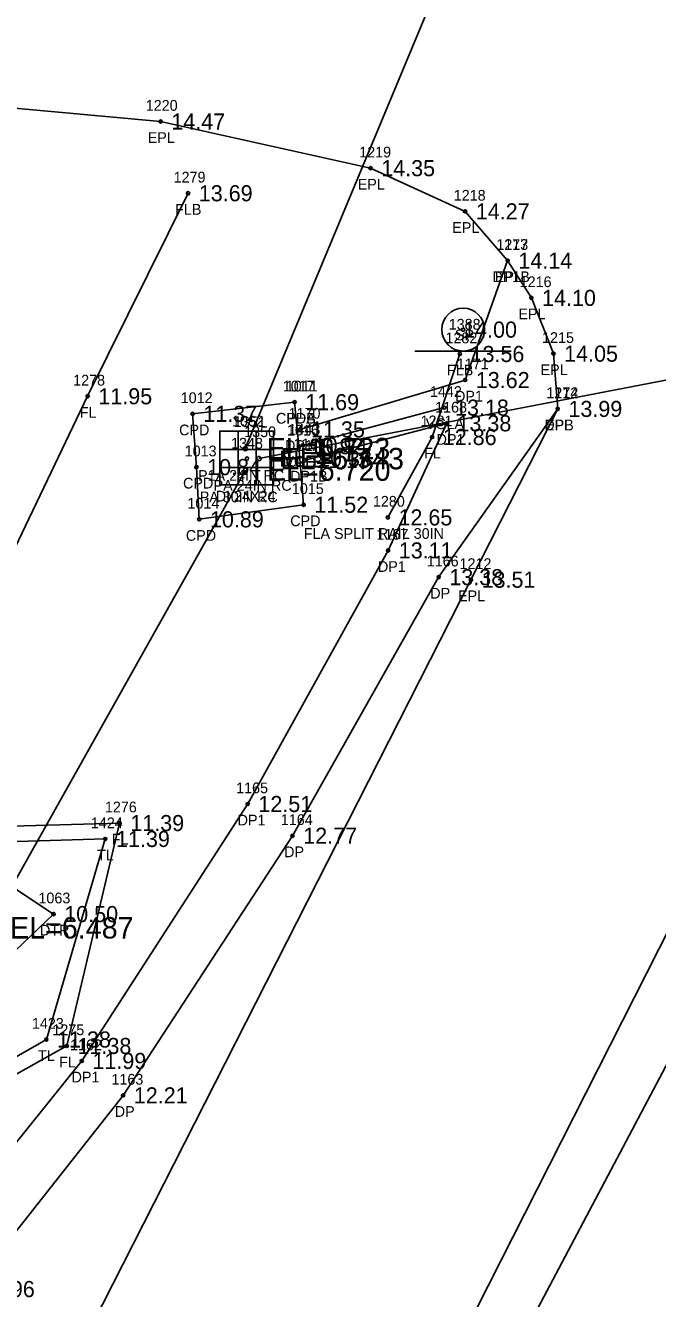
# Model space of a CAD drawing. Extents: x 2072307 to 2072993, y 127574 to 129736.
# Drawn here: x 2072771.4 to 2072830.3, y 128472.9 to 128591.5 of the extents above; entities that cross this region are included whole.
import ezdxf

# ---------------------------------------------------------------- set-up
doc = ezdxf.new("R2010")
doc.units = 0
for name, color, linetype in [('RD_EX_BldgApp', 7, 'Continuous'), ('RD_EX_BldgApp_txCode', 7, 'Continuous'), ('RD_EX_Conc', 7, 'Continuous'), ('RD_EX_Conc_txCode', 7, 'Continuous'), ('RD_EX_DR_Inlet', 7, 'Continuous'), ('RD_EX_DR_Inlet_txCode', 7, 'Continuous'), ('RD_EX_DR_Pipe', 7, 'Continuous'), ('RD_EX_DR_Pipe_txCode', 7, 'Continuous'), ('RD_EX_Driveway', 7, 'Continuous'), ('RD_EX_Driveway_txCode', 7, 'Continuous'), ('RD_EX_Fence_Other', 7, 'Continuous'), ('RD_EX_Fence_Other_txCode', 7, 'Continuous'), ('RD_EX_H2O', 7, 'Continuous'), ('RD_EX_H2O_txCode', 7, 'Continuous'), ('RD_EX_Road', 7, 'Continuous'), ('RD_EX_Road_txCode', 7, 'Continuous'), ('RD_EX_TX_BldgApp_ELEV', 7, 'Continuous'), ('RD_EX_TX_Conc_ELEV', 7, 'Continuous'), ('RD_EX_TX_DR_Inlet_ELEV', 7, 'Continuous'), ('RD_EX_TX_Driveway_ELEV', 7, 'Continuous'), ('RD_EX_TX_Fence_Other_ELEV', 7, 'Continuous'), ('RD_EX_TX_H2O_ELEV', 7, 'Continuous'), ('RD_EX_TX_Road_ELEV', 7, 'Continuous'), ('RD_EX_TX_VEG_ELEV', 7, 'Continuous'), ('RD_EX_VEG', 7, 'Continuous'), ('RD_EX_VEG_txCode', 7, 'Continuous'), ('RD_SMD_Locator', 7, 'Continuous'), ('RD_TX_Pipe_ElevEX', 7, 'Continuous')]:
    doc.layers.add(name, color=color, linetype=linetype)

msp = doc.modelspace()

# ---------------------------------------------------------------- linework, layer by layer
at = {"layer": 'RD_EX_BldgApp'}
msp.add_line((2072807.67, 128561.15), (2072816.67, 128561.15), dxfattribs=at)
msp.add_circle((2072812.19, 128563.17), 2, dxfattribs=at)
at = {"layer": 'RD_EX_Conc'}
msp.add_lwpolyline([(2072796.46, 128556.41), (2072786.95, 128555.32), (2072787.31, 128550.36), (2072787.57, 128545.49), (2072797.31, 128546.85), (2072796.87, 128552.3), (2072796.46, 128556.41)], dxfattribs=at)
at = {"layer": 'RD_EX_DR_Inlet'}
for p, q in [((2072791.19, 128553.71), (2072791.19, 128548.71)), ((2072792.89, 128553.71), (2072792.89, 128548.71)), ((2072789.49, 128552.01), (2072794.49, 128552.01)), ((2072789.49, 128550.31), (2072794.49, 128550.31))]:
    msp.add_line(p, q, dxfattribs=at)
msp.add_lwpolyline([(2072789.49, 128548.71), (2072789.49, 128553.71), (2072794.49, 128553.71), (2072794.49, 128548.71)], close=True, dxfattribs=at)
at = {"layer": 'RD_EX_DR_Pipe'}
for p, q in [((2072791.86, 128552.08), (2072822.76, 128626.35)), ((2072793.14, 128551.15), (2072922.75, 128576.12)), ((2072791.89, 128550.08), (2072767.92, 128507.42))]:
    msp.add_line(p, q, dxfattribs=at)
at = {"layer": 'RD_EX_Driveway'}
for points in [[(2072797, 128553.87), (2072812.37, 128558.47), (2072816.34, 128569.6)], [(2072694.21, 128239.74), (2072695.7, 128289.15), (2072695.56, 128330.43), (2072696.37, 128337.85), (2072700.81, 128345.17), (2072711.22, 128347.96), (2072719.56, 128349.59), (2072725.15, 128351.26), (2072733.07, 128358.33), (2072734.19, 128365.42), (2072741.79, 128414.16), (2072748.82, 128445.27), (2072754.15, 128456.57), (2072759.92, 128465.41), (2072766.21, 128473.75), (2072780.47, 128491.8), (2072796.27, 128516), (2072809.9, 128540.1), (2072821.01, 128555.78)], [(2072689.37, 128239.9), (2072690.93, 128289.43), (2072690.32, 128330.24), (2072690.73, 128338.81), (2072697.63, 128350.77), (2072709.38, 128353.48), (2072719, 128355.15), (2072723.52, 128356.83), (2072727.18, 128360.82), (2072729.07, 128366.04), (2072736.87, 128415.65), (2072743.44, 128446.63), (2072749.73, 128459.37), (2072755.76, 128468.63), (2072761.76, 128476.56), (2072776.61, 128495.01), (2072792.09, 128518.96), (2072805.19, 128542.59), (2072810.66, 128554.44), (2072797.46, 128551.01)]]:
    msp.add_lwpolyline(points, dxfattribs=at)
at = {"layer": 'RD_EX_Fence_Other'}
for points in [[(2072717.23, 128356.49), (2072726.05, 128417.31), (2072734.38, 128449.46), (2072744.93, 128479.47), (2072775.22, 128496.41), (2072780.14, 128517.18), (2072757.78, 128516.55), (2072777.16, 128556.96), (2072786.53, 128575.88)], [(2072805.16, 128545.67), (2072809.29, 128553.16), (2072811.88, 128560.9)]]:
    msp.add_lwpolyline(points, dxfattribs=at)
at = {"layer": 'RD_EX_H2O'}
msp.add_lwpolyline([(2072699.9, 128366.65), (2072717.3, 128368.56), (2072719.94, 128447.6), (2072741.08, 128477.29), (2072773.98, 128508.7), (2072764.73, 128514.82)], dxfattribs=at)
at = {"layer": 'RD_EX_Road'}
msp.add_line((2072810.43, 128555.9), (2072797.24, 128552.38), dxfattribs=at)
for points in [[(2072789.45, 128345.69), (2072789.46, 128382.93), (2072788.01, 128408.09), (2072794.06, 128431.26), (2072804.3, 128453.88), (2072840.7, 128525.64), (2072876.68, 128596.08), (2072888.72, 128617.36), (2072893.24, 128622.62), (2072899.84, 128627.36), (2072910.72, 128631.76), (2072918.79, 128632.23), (2072935.82, 128627.02), (2072957.37, 128619.98)], [(2072775.68, 128466.69), (2072812.91, 128539.86), (2072821.01, 128555.78), (2072820.61, 128560.93), (2072818.55, 128566.13), (2072816.34, 128569.6), (2072812.37, 128574.19), (2072803.55, 128578.22), (2072783.97, 128582.57), (2072748.23, 128585.83), (2072732.11, 128585.24), (2072729.74, 128580.26), (2072735.29, 128576), (2072744.65, 128575.04), (2072744.47, 128530.69), (2072748.67, 128517.7), (2072747.55, 128516.74), (2072744.67, 128526.22), (2072742.83, 128527.54), (2072739.81, 128528.33), (2072729.54, 128527.67)]]:
    msp.add_lwpolyline(points, dxfattribs=at)
at = {"layer": 'RD_EX_VEG'}
for points in [[(2072791.29, 128345.62), (2072800.72, 128429.53), (2072808.9, 128452.58), (2072870.32, 128568.64), (2072876.57, 128573.6), (2072916.77, 128564.68), (2072920.97, 128548.67)], [(2072681.97, 128364.24), (2072716.35, 128365.68), (2072731.52, 128450.35), (2072742.94, 128479.7), (2072773.31, 128497.01), (2072778.81, 128515.7), (2072758.24, 128515.09)]]:
    msp.add_lwpolyline(points, dxfattribs=at)
at = {"layer": 'RD_SMD_Locator'}
for centre, radius in [((2072783.97, 128582.57), 0.15), ((2072803.55, 128578.22), 0.15), ((2072786.53, 128575.88), 0.15), ((2072812.37, 128574.19), 0.15), ((2072816.34, 128569.6), 0.15), ((2072816.34, 128569.6), 0.15), ((2072818.55, 128566.13), 0.15), ((2072812.19, 128563.17), 0.15), ((2072811.88, 128560.9), 0.15), ((2072820.61, 128560.93), 0.15), ((2072812.37, 128558.47), 0.15), ((2072777.16, 128556.96), 0.15), ((2072796.46, 128556.41), 0.15), ((2072796.46, 128556.41), 0.15), ((2072786.95, 128555.32), 0.15), ((2072810.43, 128555.9), 0.15), ((2072821.01, 128555.78), 0.15), ((2072821.01, 128555.78), 0.15), ((2072810.66, 128554.44), 0.15), ((2072797, 128553.87), 0.15), ((2072809.29, 128553.16), 0.15), ((2072791.86, 128552.08), 0.2), ((2072796.87, 128552.3), 0.15), ((2072797.24, 128552.38), 0.15), ((2072792.03, 128551.15), 0.15), ((2072793.14, 128551.15), 0.2), ((2072797.46, 128551.01), 0.15), ((2072787.31, 128550.36), 0.15), ((2072791.89, 128550.08), 0.2), ((2072797.31, 128546.85), 0.15), ((2072805.16, 128545.67), 0.15), ((2072787.57, 128545.49), 0.15), ((2072805.19, 128542.59), 0.15), ((2072809.9, 128540.1), 0.15), ((2072812.91, 128539.86), 0.15), ((2072792.09, 128518.96), 0.15), ((2072780.14, 128517.18), 0.15), ((2072796.27, 128516), 0.15), ((2072778.81, 128515.7), 0.15), ((2072773.98, 128508.7), 0.15), ((2072773.31, 128497.01), 0.15), ((2072775.22, 128496.41), 0.15), ((2072776.61, 128495.01), 0.15), ((2072780.47, 128491.8), 0.15)]:
    msp.add_circle(centre, radius, dxfattribs=at)

# ---------------------------------------------------------------- texts
at = {"layer": 'RD_EX_BldgApp_txCode'}
for s, p in [('1388', (2072810.84, 128563.17)), ('SP', (2072811.41, 128562.17))]:
    msp.add_text(s, height=1, dxfattribs=at).set_placement(p)
at = {"layer": 'RD_EX_Conc_txCode'}
for s, p in [('1017', (2072795.36, 128557.41)), ('1011', (2072795.64, 128557.41)), ('1012', (2072785.84, 128556.32)), ('CPDA', (2072794.72, 128554.41)), ('CPDB', (2072794.73, 128554.41)), ('CPD', (2072785.69, 128553.32)), ('1016', (2072795.75, 128553.3)), ('1013', (2072786.21, 128551.36)), ('CPD', (2072795.62, 128550.3)), ('CPD', (2072786.06, 128548.36)), ('1015', (2072796.21, 128547.85)), ('1014', (2072786.47, 128546.49)), ('CPD', (2072796.06, 128544.85)), ('CPD', (2072786.32, 128543.49))]:
    msp.add_text(s, height=1, dxfattribs=at).set_placement(p)
at = {"layer": 'RD_EX_DR_Inlet_txCode'}
for s, p in [('1062', (2072790.62, 128554.15)), ('DI 24X24', (2072789.11, 128547.15))]:
    msp.add_text(s, height=1, dxfattribs=at).set_placement(p)
at = {"layer": 'RD_EX_DR_Pipe_txCode'}
for s, p in [('1351', (2072790.8, 128554.08)), ('1350', (2072791.76, 128553.15)), ('1348', (2072790.54, 128552.08)), ('P1A 24IN RC', (2072787.46, 128549.08)), ('PA 24IN RC', (2072788.91, 128548.15)), ('PA 30IN RC', (2072787.61, 128547.08))]:
    msp.add_text(s, height=1, dxfattribs=at).set_placement(p)
at = {"layer": 'RD_EX_Driveway_txCode'}
for s, p in [('1173', (2072815.28, 128570.6)), ('DP1B', (2072814.92, 128567.6)), ('1171', (2072811.59, 128559.47)), ('1172', (2072819.95, 128556.78)), ('1168', (2072809.57, 128555.44)), ('DP1', (2072811.43, 128556.47)), ('1170', (2072795.9, 128554.87)), ('DPB', (2072819.76, 128553.78)), ('1169', (2072796.38, 128552.01)), ('DP1', (2072809.71, 128552.44)), ('DP1A', (2072795.57, 128551.87)), ('DP1B', (2072796.05, 128549.01)), ('1167', (2072804.1, 128543.59)), ('DP1', (2072804.24, 128540.59)), ('1166', (2072808.79, 128541.1)), ('DP', (2072809.12, 128538.1)), ('1165', (2072791.01, 128519.96)), ('DP1', (2072791.15, 128516.96)), ('1164', (2072795.18, 128517)), ('DP', (2072795.49, 128514)), ('1162', (2072775.52, 128496.01)), ('DP1', (2072775.66, 128493.01)), ('1163', (2072779.38, 128492.8)), ('DP', (2072779.69, 128489.8))]:
    msp.add_text(s, height=1, dxfattribs=at).set_placement(p)
at = {"layer": 'RD_EX_Fence_Other_txCode'}
for s, p in [('1279', (2072785.18, 128576.88)), ('FLB', (2072785.32, 128573.88)), ('1282', (2072810.54, 128561.9)), ('1278', (2072775.81, 128557.96)), ('FLB', (2072810.68, 128558.9)), ('FL', (2072776.43, 128554.96)), ('1281', (2072808.22, 128554.16)), ('FL', (2072808.55, 128551.16)), ('1280', (2072803.77, 128546.67)), ('FLA SPLIT RAIL 30IN', (2072797.32, 128543.67)), ('1276', (2072778.77, 128518.18)), ('FL', (2072779.41, 128515.18)), ('1275', (2072773.87, 128497.41)), ('FL', (2072774.49, 128494.41))]:
    msp.add_text(s, height=1, dxfattribs=at).set_placement(p)
at = {"layer": 'RD_EX_H2O_txCode'}
for s, p in [('1063', (2072772.57, 128509.7)), ('DTR', (2072772.71, 128506.7))]:
    msp.add_text(s, height=1, dxfattribs=at).set_placement(p)
at = {"layer": 'RD_EX_Road_txCode'}
for s, p in [('1220', (2072782.58, 128583.57)), ('EPL', (2072782.76, 128580.57)), ('1219', (2072802.49, 128579.22)), ('EPL', (2072802.35, 128576.22)), ('1218', (2072811.31, 128575.19)), ('EPL', (2072811.17, 128572.19)), ('1217', (2072815.28, 128570.6)), ('EPL', (2072815.14, 128567.6)), ('1216', (2072817.46, 128567.13)), ('EPL', (2072817.34, 128564.13)), ('1215', (2072819.55, 128561.93)), ('EPL', (2072819.41, 128558.93)), ('1442', (2072809.09, 128556.9)), ('1214', (2072819.95, 128556.78)), ('1443', (2072795.89, 128553.38)), ('VGLA', (2072808.7, 128553.9)), ('EPL', (2072819.81, 128553.78)), ('VGLB', (2072795.52, 128550.38)), ('1212', (2072811.85, 128540.86)), ('EPL', (2072811.71, 128537.86))]:
    msp.add_text(s, height=1, dxfattribs=at).set_placement(p)
at = {"layer": 'RD_EX_TX_BldgApp_ELEV'}
msp.add_text('14.00', height=1.5, dxfattribs=at).set_placement((2072812.19, 128562.42))
at = {"layer": 'RD_EX_TX_Conc_ELEV'}
for s, p in [('11.69', (2072797.46, 128555.66)), ('11.69', (2072797.46, 128555.66)), ('11.37', (2072787.95, 128554.57)), ('10.92', (2072797.87, 128551.55)), ('10.84', (2072788.31, 128549.61)), ('11.52', (2072798.31, 128546.1)), ('10.89', (2072788.57, 128544.74))]:
    msp.add_text(s, height=1.5, dxfattribs=at).set_placement(p)
at = {"layer": 'RD_EX_TX_DR_Inlet_ELEV'}
msp.add_text('EL=10.38', height=1.5, dxfattribs=at).set_placement((2072795.03, 128550.4))
at = {"layer": 'RD_EX_TX_Driveway_ELEV'}
for s, p in [('14.14', (2072817.34, 128568.85)), ('13.62', (2072813.37, 128557.72)), ('13.99', (2072822.01, 128555.03)), ('11.35', (2072798, 128553.12)), ('13.38', (2072811.66, 128553.69)), ('11.13', (2072798.46, 128550.26)), ('13.11', (2072806.19, 128541.84)), ('13.38', (2072810.9, 128539.35)), ('12.51', (2072793.09, 128518.21)), ('12.77', (2072797.27, 128515.25)), ('11.99', (2072777.61, 128494.26)), ('12.21', (2072781.47, 128491.05)), ('11.96', (2072767.21, 128473))]:
    msp.add_text(s, height=1.5, dxfattribs=at).set_placement(p)
at = {"layer": 'RD_EX_TX_Fence_Other_ELEV'}
for s, p in [('13.69', (2072787.53, 128575.13)), ('13.56', (2072812.88, 128560.15)), ('11.95', (2072778.16, 128556.21)), ('12.86', (2072810.29, 128552.41)), ('12.65', (2072806.16, 128544.92)), ('11.39', (2072781.14, 128516.43)), ('11.38', (2072776.22, 128495.66))]:
    msp.add_text(s, height=1.5, dxfattribs=at).set_placement(p)
at = {"layer": 'RD_EX_TX_H2O_ELEV'}
msp.add_text('10.50', height=1.5, dxfattribs=at).set_placement((2072774.98, 128507.95))
at = {"layer": 'RD_EX_TX_Road_ELEV'}
for s, p in [('14.47', (2072784.97, 128581.82)), ('14.35', (2072804.55, 128577.47)), ('14.27', (2072813.37, 128573.44)), ('14.14', (2072817.34, 128568.85)), ('14.10', (2072819.55, 128565.38)), ('14.05', (2072821.61, 128560.18)), ('13.18', (2072811.43, 128555.15)), ('13.99', (2072822.01, 128555.03)), ('10.94', (2072798.24, 128551.63)), ('13.51', (2072813.91, 128539.11))]:
    msp.add_text(s, height=1.5, dxfattribs=at).set_placement(p)
at = {"layer": 'RD_EX_TX_VEG_ELEV'}
for s, p in [('11.39', (2072779.81, 128514.95)), ('11.38', (2072774.31, 128496.26))]:
    msp.add_text(s, height=1.5, dxfattribs=at).set_placement(p)
at = {"layer": 'RD_EX_VEG_txCode'}
for s, p in [('1424', (2072777.46, 128516.7)), ('TL', (2072778.04, 128513.7)), ('1423', (2072771.96, 128498.01)), ('TL', (2072772.54, 128495.01))]:
    msp.add_text(s, height=1, dxfattribs=at).set_placement(p)
at = {"layer": 'RD_TX_Pipe_ElevEX'}
for s, p in [('EL=6.723', (2072793.86, 128551.08)), ('EL=6.743', (2072795.14, 128550.15)), ('EL=6.720', (2072793.89, 128549.08)), ('EL=6.487', (2072769.92, 128506.42))]:
    msp.add_text(s, height=2, dxfattribs=at).set_placement(p)

doc.saveas('drawing.dxf')
